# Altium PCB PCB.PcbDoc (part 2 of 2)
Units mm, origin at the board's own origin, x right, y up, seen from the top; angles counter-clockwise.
Board outline 73.15 x 70.89 mm, 4 copper layers (Top Layer, Int1 (GND), Int2 (PWR), Bottom Layer), stack 1.369 mm thick; 101 components, 61 nets, 289 pads, 185 vias.
Unrouted connection lines stored in the file: 20.
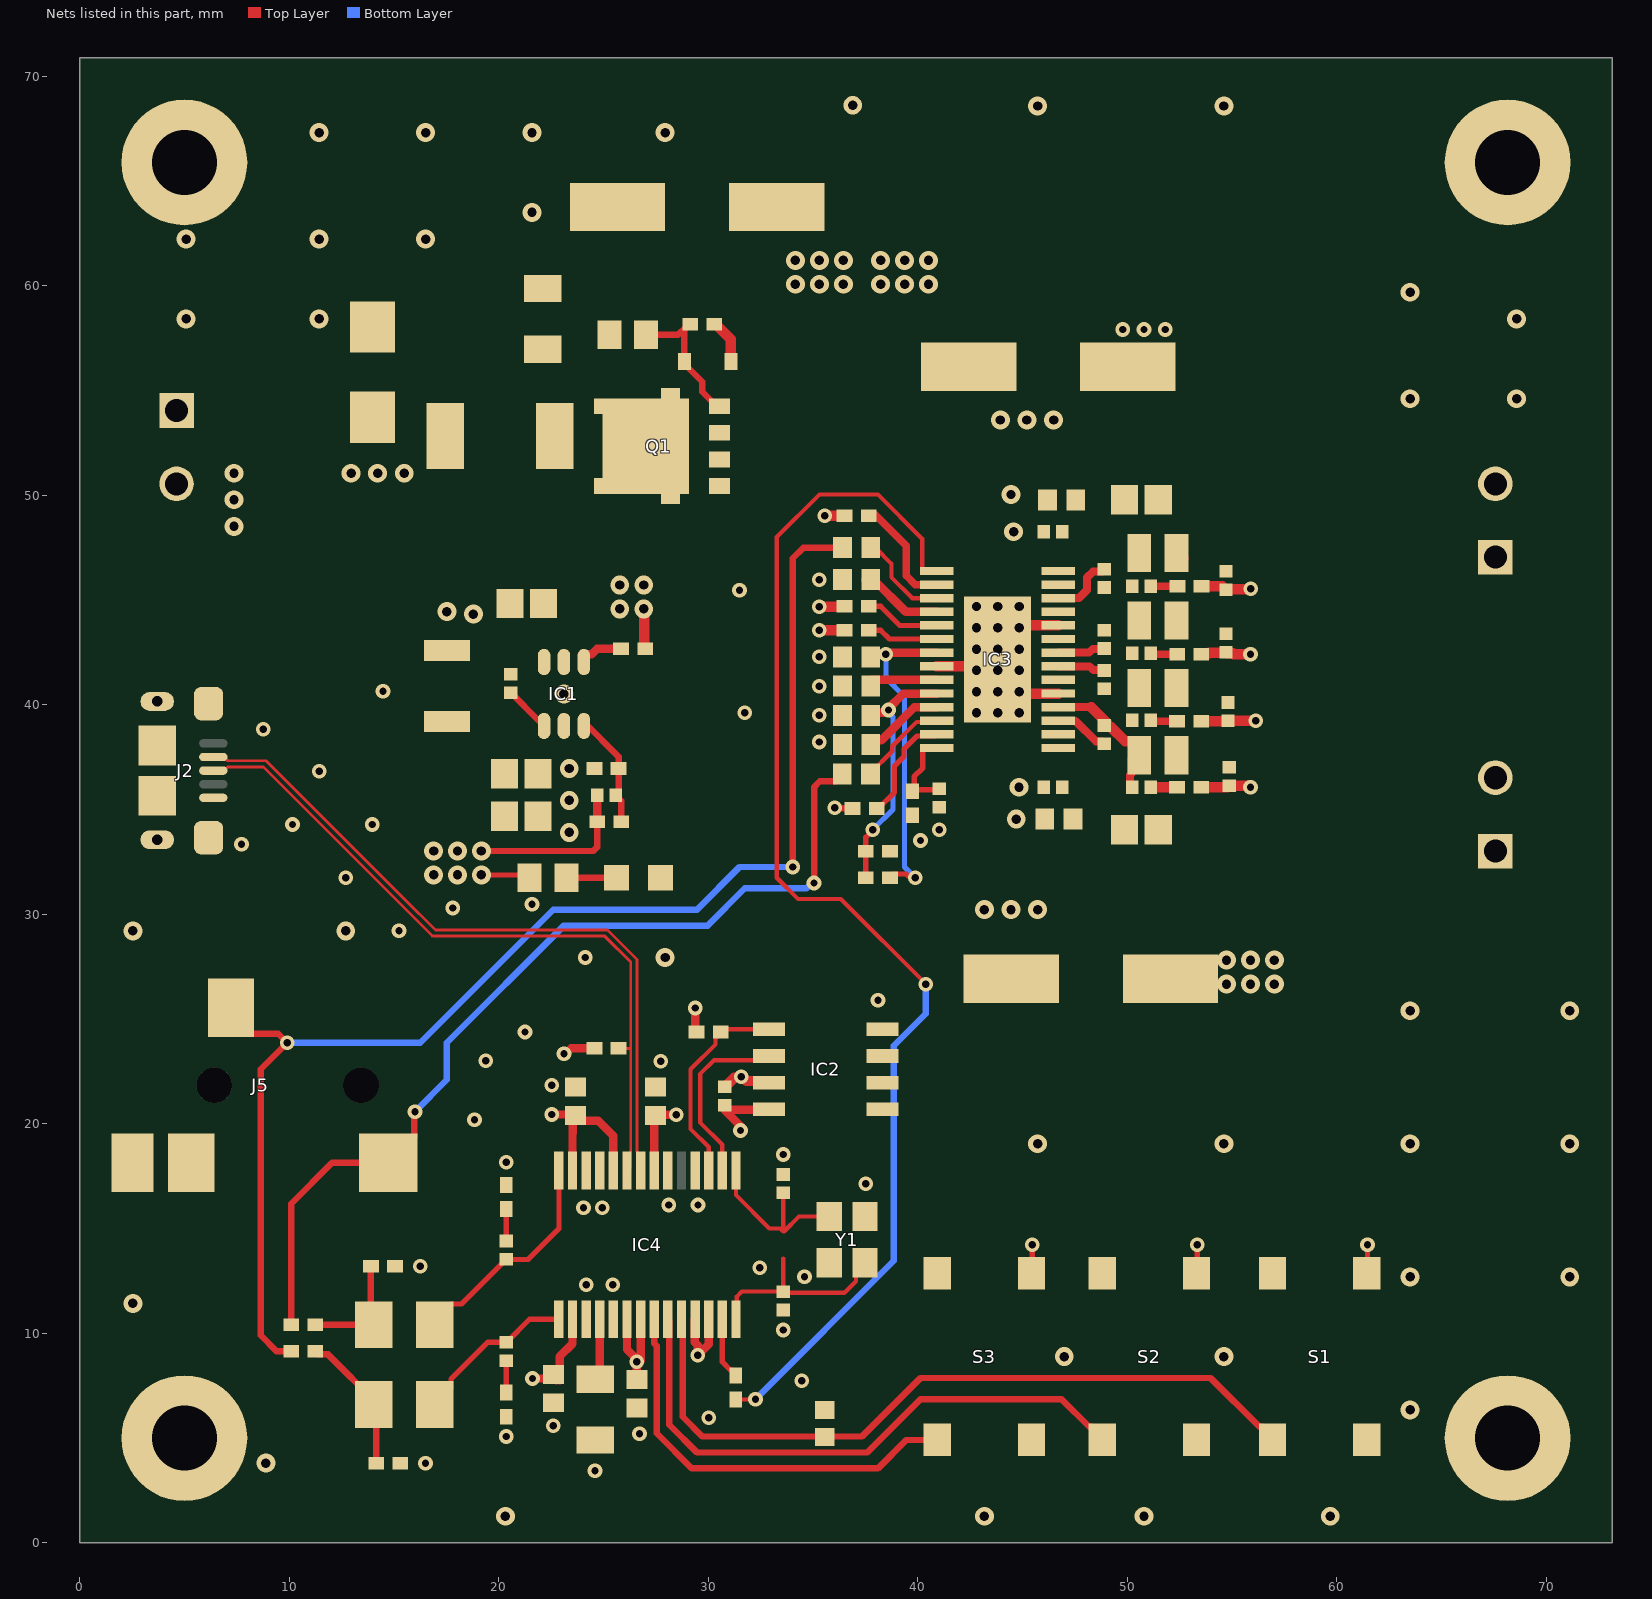
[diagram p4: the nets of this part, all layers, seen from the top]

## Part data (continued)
R4: library part RCG0402100KFKED, "RES SMD 100K OHM 1% 1/16W 0402", Device Package="0402 (1005 Metric)", Manufacturer="Vishay Dale", Operating Temperature="-55°C ~ 155°C", Power (Watts)="0.063W, 1/16W", Resistance="100 kOhms", Supplier Device Package=0402, Supplier Part Number 1=541-1751-1-ND, Temperature Coefficient=±100ppm/°C, Tolerance=±1%
R5 R7: library part SR0805JR-7W1KL, "RES 1K OHM 5% 1/4W 0805", Device Package="0805 (2012 Metric)", Manufacturer=Yageo, Operating Temperature="-55°C ~ 155°C", Power (Watts)="0.25W, 1/4W", Ratings=AEC-Q200, Supplier Device Package=0805, Supplier Part Number 1=YAG6171CT-ND, Temperature Coefficient=±100ppm/°C, Tolerance=±5%
R8: library part RMCF0603JT1M00, "RES 1M OHM 5% 1/10W 0603", Device Package="0603 (1608 Metric)", Manufacturer="Stackpole Electronics Inc", Operating Temperature="-55°C ~ 155°C", Power (Watts)="0.1W, 1/10W", Ratings=AEC-Q200, Supplier Device Package=0603, Supplier Part Number 1=RMCF0603JT1M00CT-ND, Temperature Coefficient=±200ppm/°C, Tolerance=±5%
R9 R23 R28 R29: library part JR0402X20E, "0402 20 AMP JUMPER", Device Package="0402 (1005 Metric)", Manufacturer=Ohmite, Operating Temperature="-55°C ~ 150°C", Power (Watts)="0.2W, 1/5W", Supplier Device Package=0402, Supplier Part Number 1=JR0402X20ECT-ND, Tolerance=Jumper
R11 R13 R14 R22: library part RCG0402100KFKED, "RES SMD 100K OHM 1% 1/16W 0402", Device Package="0402 (1005 Metric)", Manufacturer="Vishay Dale", Operating Temperature="-55°C ~ 155°C", Power (Watts)="0.063W, 1/16W", Supplier Device Package=0402, Supplier Part Number 1=541-1751-1-ND, Temperature Coefficient=±100ppm/°C, Tolerance=±1%
R12 R17 R20 R21: library part RMCF0402FT10R0, "RES 10 OHM 1% 1/16W 0402", Device Package="0402 (1005 Metric)", Manufacturer="Stackpole Electronics Inc", Operating Temperature="-55°C ~ 155°C", Power (Watts)="0.063W, 1/16W", Ratings=AEC-Q200, Supplier Device Package=0402, Supplier Part Number 1=RMCF0402FT10R0CT-ND, Temperature Coefficient=±100ppm/°C, Tolerance=±1%
R15: library part RMCF0402FT3K30, "RES 3.3K OHM 1% 1/16W 0402", Device Package="0402 (1005 Metric)", Manufacturer="Stackpole Electronics Inc", Operating Temperature="-55°C ~ 155°C", Power (Watts)="0.063W, 1/16W", Ratings=AEC-Q200, Supplier Device Package=0402, Supplier Part Number 1=RMCF0402FT3K30CT-ND, Temperature Coefficient=±100ppm/°C, Tolerance=±1%
R19: library part CRCW04021K50FKEDHP, "RES SMD 1.5K OHM 1% 1/5W 0402"
R24 R25: library part RK73H1ETTP1690F, "RES 169 OHM 1% 1/10W 0402", Device Package="0402 (1005 Metric)", Manufacturer="KOA Speer Electronics, Inc.", Operating Temperature="-55°C ~ 155°C", Power (Watts)="0.1W, 1/10W", Ratings=AEC-Q200, Supplier Device Package=0402, Supplier Part Number 1=2019-RK73H1ETTP1690FCT-ND, Temperature Coefficient=±100ppm/°C, Tolerance=±1%
R26 R27: library part ERJ-2RKF16R0X, "RES SMD 16 OHM 1% 1/10W 0402", Device Package="0402 (1005 Metric)", Manufacturer="Panasonic Electronic Components", Operating Temperature="-55°C ~ 155°C", Power (Watts)="0.1W, 1/10W", Ratings=AEC-Q200, Supplier Device Package=0402, Supplier Part Number 1=P16.0LCT-ND, Temperature Coefficient=±100ppm/°C, Tolerance=±1%
S1 S2 S3: "SWITCH TACTILE SPST-NO 0.05A 12V", Contact Rating @ Voltage="0.05A @ 12VDC", Manufacturer=C&K, Operating Force=160gf, Operating Temperature="-20°C ~ 60°C", Supplier Part Number 1=CKN9112CT-ND
Y1: library part ABM8G-12.000MHZ-B4Y-T, "CRYSTAL 12.0000MHZ 10PF SMD", Device Package="4-SMD, No Lead", ESR (Equivalent Series Resistance)="120 Ohms", Frequency Stability=±30ppm, Load Capacitance=10pF, Manufacturer="Abracon LLC", Operating Mode=Fundamental, Operating Temperature="-20°C ~ 70°C", Supplier Part Number 1=535-10283-1-ND

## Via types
v1: diameter 0.9, hole 0.45, Top Layer to Bottom Layer, tented both sides, 105 vias
v2: diameter 0.7, hole 0.35, Top Layer to Bottom Layer, tented both sides, 80 vias

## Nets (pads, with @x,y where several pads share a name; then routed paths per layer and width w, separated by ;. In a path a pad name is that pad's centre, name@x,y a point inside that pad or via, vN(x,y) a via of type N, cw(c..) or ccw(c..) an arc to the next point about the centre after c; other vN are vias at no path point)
+3V3: C4.2 C5.2 C6.2 C10.2 C25.2 C29.2 C36.2 C37.2 IC2.8 IC4.7 IC4.10 IC4.13 IC4.16 IC4.20 IC4.21 IC4.25 IC4.26 L1.2 R2.1 R7.2 R15.1 R19.1 S1.3 S1.4 S2.3 S2.4 S3.3 S3.4 | length 45.3
  Top Layer w0.254: v1(19.177,31.881) 21.346,31.881 R7.2@21.477,31.75 ; S3.4@45.43,12.865 45.466,12.901 v2(45.466,14.224) ; S2.4@53.304,12.865 53.34,12.901 v2(53.34,14.224) ; S1.4@61.432,12.865 61.468,12.901 v2(61.468,14.224)
  Top Layer w0.305: v1(19.177,33.024) 24.511,33.024 24.698,33.211 R2.1@24.698,34.421
  Top Layer w0.4: v2(21.613,7.848) 22.669,7.848 C36.2@22.756,7.761 ; v2(22.527,20.447) 23.63,20.447 C37.2@23.67,20.407 ; C36.2@22.908,7.761 22.908,8.89 23.524,9.506 IC4.16@23.524,10.674 ; v2(23.114,23.349) 23.195,23.349 23.449,23.603 R19.1@24.571,23.603 ; IC4.13@23.524,17.774 23.524,19.539 23.543,19.558 23.543,20.28 C37.2@23.67,20.407 ; R2.1@24.698,34.421 24.706,34.429 C4.2@24.706,35.691 ; IC4.10@25.474,17.774 25.474,19.43 24.748,20.157 23.92,20.157 C37.2@23.67,20.407 ; IC4.20@26.124,10.674 26.124,9.23 26.718,8.636 26.774,8.692 IC4.21@26.774,10.674 ; C29.2@26.592,7.793 v2(26.592,8.642) ; IC4.7@27.424,17.774 27.424,20.351 C25.2@27.48,20.407 27.511,20.437 v2(28.469,20.437) ; R15.1@29.37,24.384 29.385,24.399 v2(29.385,25.527) ; IC4.25@29.374,10.674 29.351,10.65 29.351,9.585 29.494,9.441 v2(29.494,8.949) 30.02,9.476 30.02,10.67 IC4.26@30.024,10.674 ; v2(31.544,19.685) 31.544,19.899 30.782,20.661 30.802,20.681 32.876,20.681 IC2.8@32.896,20.701
  other v1: 16.891,31.881 18.034,31.881 16.891,33.024 18.034,33.024
+15V: C2.1 C3.2 C11.1 C42.1 D1.2 FB5.2 FB10.2 IC1.5 Q1.1 Q1.2 Q1.3 R1.2 R3.2 R11.2 R13.2 R22.2 | length 7.1
  Top Layer w0.305: v2(36.04,35.08) 36.054,35.066 36.876,35.066 R22.2@36.89,35.052
  Top Layer w0.5: v1(26.924,44.577) 26.958,44.543 26.958,42.706 R1.2@26.991,42.672 ; R3.2@30.293,58.166 30.368,58.166 31.084,57.45 D1.2@31.084,56.388 ; v2(35.306,44.679) 35.319,44.691 36.496,44.691 R13.2@36.509,44.704 ; v2(35.56,49.022) R11.2@36.509,49.022
  other v1: 54.737,26.67 55.88,26.67 57.023,26.67 54.737,27.813 55.88,27.813 57.023,27.813 25.781,44.577 25.781,45.72 26.924,45.72 34.163,60.071 35.306,60.071 36.449,60.071 38.227,60.071 39.37,60.071 40.513,60.071 34.163,61.214 35.306,61.214 36.449,61.214 38.227,61.214 39.37,61.214 40.513,61.214
  other v2: 49.784,57.912 50.8,57.912 51.816,57.912
A_SCL: IC2.6 IC4.2 | length 8.7
  Top Layer w0.203: IC4.2@30.674,17.774 30.674,19.005 29.614,20.066 29.614,22.377 30.274,23.038 32.693,23.038 IC2.6@32.896,23.241
A_SDA: IC2.5 IC4.3 R15.2 | length 9.9
  Top Layer w0.203: IC4.3@30.024,17.774 30.024,18.893 29.158,19.76 29.158,22.607 30.347,23.796 30.347,24.06 30.797,24.511 IC2.5@32.896,24.511
AUD_D_N: IC4.8 J2.2 | length 34.4
  Top Layer w0.141: J2.2@6.379,37.51 6.888,37.51 7.066,37.332 8.896,37.332 15.39,30.838 15.494,30.734 16.979,29.249 25.189,29.249 26.596,27.842 26.596,23.622 26.596,18.686 26.62,18.662 26.62,17.928 IC4.8@26.774,17.774
AUD_D_P: IC4.9 J2.3 R19.2 | length 34.5
  Top Layer w0.141: J2.3@6.379,36.86 6.888,36.86 7.066,37.038 8.775,37.038 16.771,29.042 16.857,28.956 25.067,28.956 26.303,27.721 26.303,23.622 ; R19.2@25.721,23.603 26.284,23.603 26.303,23.622 ; IC4.9@26.124,17.774 26.279,17.928 26.279,18.662 26.303,18.686 26.303,23.622
AUDIO_INL: C32.1 J5.2 R29.1 | length 45
  Top Layer w0.305: R29.1@10.093,10.414 10.093,16.189 12.048,18.144 J5.2@14.726,18.144 15.974,19.392 15.974,20.546 v2(16.002,20.574) ; v2(35.052,31.496) 35.052,36.068 35.33,36.346 36.099,36.346 36.397,36.644 C32.1@36.397,36.694
  Bottom Layer w0.305: v2(16.002,20.574) 17.526,22.098 17.526,23.876 23.114,29.464 29.972,29.464 31.75,31.242 34.691,31.242 34.945,31.496 v2(35.052,31.496)
AUDIO_INR: C14.1 J5.3 R28.1 | length 64.7
  Top Layer w0.305: J5.3@7.226,25.544 7.226,25.244 8.174,24.296 9.486,24.296 v2(9.906,23.876) 8.636,22.606 8.636,9.906 9.398,9.144 R28.1@10.093,9.144 ; v2(34.036,32.258) 34.036,46.99 34.544,47.498 C14.1@36.409,47.498
  Bottom Layer w0.305: v2(9.906,23.876) 16.256,23.876 22.606,30.226 29.464,30.226 31.496,32.258 v2(34.036,32.258)
AVCC_MP: C19.2 IC3.7 R16.1 | length 15.9
  Top Layer w0.254: R16.1@38.675,31.75 38.848,31.923 39.451,31.923 39.539,31.835 39.793,31.835 v2(39.878,31.75)
  Top Layer w0.406: C19.2@37.759,42.291 37.957,42.489 38.028,42.418 v2(38.481,42.418) 38.552,42.489 IC3.7@40.915,42.489
  Bottom Layer w0.254: v2(38.481,42.418) 38.481,41.275 39.37,40.386 39.37,32.258 v2(39.878,31.75)
EN_AMP: IC3.1 R9.1 | length 60.5
  Top Layer w0.203: R9.1@31.328,6.83 R9.1@31.316,6.842 32.242,6.842 v2(32.258,6.858) ; v2(40.386,26.67) 36.322,30.734 34.29,30.734 33.274,31.75 33.274,48.006 35.306,50.038 38.1,50.038 40.217,47.921 40.217,46.487 40.315,46.389 IC3.1@40.915,46.389
  Bottom Layer w0.305: v2(32.258,6.858) 38.862,13.462 38.862,23.725 40.386,25.249 v2(40.386,26.67)
GAIN0: IC3.5 R13.1 | length 3.6
  Top Layer w0.254: R13.1@37.659,44.704 38.227,44.704 39.142,43.789 IC3.5@40.915,43.789
GAIN1: IC3.6 R14.1 | length 3.4
  Top Layer w0.254: R14.1@37.659,43.561 38.227,43.561 38.649,43.139 IC3.6@40.915,43.139
GND: C2.2 C3.1 C5.1 C6.1 C7.1 C8.2 C9.2 C10.1 C11.2 C12.1 C13.1 C16.1 C18.1 C19.1 C22.1 C23.2 C25.1 C27.1 C28.1 C29.1 C30.1 C31.1 C35.1 C36.1 C37.1 C38.1 C40.1 C41.1 C42.2 D2.1 D3.2 H1.1 H2.1 H3.1 H4.1 IC1.2 IC2.1 IC2.2 IC2.3 IC2.4 IC2.7 IC3.8 IC3.19 IC3.24 IC3.EPAD IC4.4 IC4.6 IC4.11 IC4.12 IC4.17 IC4.19 J1.1 J2.5 J2.S J5.1 J5.4 R4.2 R5.1 R12.2 R14.2 R17.2 R18.2 R20.1 R21.2 R23.1 R24.1 R25.1 R26.1 R27.1 Y1.2 Y1.4 | length 18.9
  Top Layer w0.5: C10.1@30.782,21.776 30.802,21.776 v2@31.233,22.206 ; v2(31.579,22.244) 31.633,22.244 31.831,22.046 32.821,22.046 IC2.7@32.896,21.971 ; v2(35.306,43.561) R14.2@36.509,43.561 ; IC3.8@40.915,41.839 42.611,41.839 v1(42.805,41.645) ; v1(44.837,40.629) 44.927,40.539 IC3.19@46.715,40.539 ; v1(44.837,43.677) 44.949,43.789 IC3.24@46.715,43.789 ; R21.2@53.525,36.068 54.776,36.068 54.844,36.136 C35.1@54.864,36.136 55.758,36.136 55.826,36.068 v2(55.88,36.068) ; R20.1@53.525,39.21 53.535,39.221 54.797,39.221 C27.1@54.807,39.231 54.812,39.236 56.125,39.236 v2(56.13,39.24) ; R17.2@53.534,42.418 53.584,42.468 53.905,42.468 53.922,42.484 C22.1@54.681,42.484 ; R12.2@53.545,45.654 54.538,45.654 54.692,45.5 C18.1@54.712,45.5 54.729,45.517 55.882,45.517 v2(55.899,45.534) ; C22.1@54.712,42.514 54.762,42.464 55.028,42.464 55.074,42.418 v2(55.88,42.418)
  other v1: 20.32,1.27 43.18,1.27 50.8,1.27 59.69,1.27 8.89,3.81 63.5,6.35 46.99,8.89 54.61,8.89 2.54,11.43 63.5,12.7 71.12,12.7 45.72,19.05 54.61,19.05 63.5,19.05 71.12,19.05 63.5,25.4 71.12,25.4 27.94,27.94 2.54,29.21 12.7,29.21 43.18,30.226 44.45,30.226 45.72,30.226 23.368,33.913 44.704,34.544 23.368,35.437 44.831,36.068 23.368,36.961 42.805,39.613 43.821,39.613 44.837,39.613 23.114,40.517 42.805,40.629 43.821,40.629 43.821,41.645 44.837,41.645 42.805,42.661 43.821,42.661 44.837,42.661 42.805,43.677 43.821,43.677 18.796,44.327 17.526,44.45 42.805,44.693 43.821,44.693 44.837,44.693 44.577,48.26 44.45,50.038 43.942,53.594 45.212,53.594 46.482,53.594 63.5,54.61 68.58,54.61 5.08,58.42 11.43,58.42 68.58,58.42 63.5,59.69 5.08,62.23 11.43,62.23 16.51,62.23 21.59,63.5 11.43,67.31 16.51,67.31 21.59,67.31 27.94,67.31 45.72,68.58 54.61,68.58 36.901,68.618
  other v2: 24.597,3.448 16.51,3.81 20.368,5.08 26.718,5.207 22.602,5.587 30.02,5.969 34.465,7.747 33.576,10.16 24.178,12.319 25.448,12.319 34.592,12.7 32.459,13.132 16.256,13.208 24.051,16.002 24.94,16.002 28.115,16.129 29.512,16.129 37.513,17.145 20.368,18.161 33.576,18.542 18.844,20.193 22.527,21.844 27.734,22.987 19.383,23.02 21.257,24.384 38.1,25.908 24.13,27.94 15.24,29.21 17.81,30.303 21.59,30.48 12.7,31.75 7.726,33.345 40.132,33.528 41.021,34.036 10.16,34.29 13.97,34.29 11.43,36.83 35.306,38.227 8.759,38.831 35.306,39.497 31.75,39.624 14.478,40.64 35.306,40.894 35.306,42.291 31.496,45.466 35.306,45.974
LOUTN: C27.2 FB8.2 J4.2
LOUTP: C35.2 FB9.2 J4.1
NetC1_1: C1.1 IC1.1 | length 2.1
  Top Layer w0.305: C1.1@20.574,40.585 21.913,39.246 IC1.1@22.164,39.246
NetC1_2: C1.2 IC1.6 L1.1
NetC4_1: C4.1 IC1.3 R2.2 R4.1 | length 5.7
  Top Layer w0.305: IC1.3@24.064,39.246 24.064,39.186 25.721,37.529 R4.1@25.721,36.961 25.721,35.826 C4.1@25.586,35.691 25.848,35.429 R2.2@25.848,34.421
NetC7_2: C7.2 F1.2 Q1.5 Q1.6 Q1.7 Q1.8 Q1.9
NetC8_1: C8.1 IC4.1 R8.1 Y1.1 | length 8.5
  Top Layer w0.203: IC4.1@31.324,17.774 31.324,16.603 32.916,15.012 33.439,15.012 33.576,14.874 ; C8.1@33.576,16.705 33.576,14.874 ; Y1.1@35.774,15.578 34.33,15.578 33.626,14.874 33.576,14.874
NetC9_1: C9.1 IC4.28 R8.2 Y1.3 | length 9.8
  Top Layer w0.203: IC4.28@31.324,10.674 31.366,10.716 31.366,11.76 31.603,11.997 C9.1@33.576,11.997 ; 33.576,13.574 C9.1@33.576,11.997 ; Y1.3@37.474,13.378 37.052,12.955 37.052,12.492 36.497,11.938 33.635,11.938 C9.1@33.576,11.997
NetC12_2: C12.2 C13.2 FB5.1 IC3.27 IC3.28
NetC14_2: C14.2 IC3.3 | length 4.5
  Top Layer w0.203: C14.2@37.759,47.498 37.979,47.498 38.748,46.729 38.748,46.084 39.743,45.089 IC3.3@40.915,45.089
NetC15_1: C15.1 IC3.26 | length 3.1
  Top Layer w0.381: IC3.26@46.715,45.089 46.724,45.099 47.703,45.099 48.078,45.473 48.078,46.075 48.372,46.368 48.784,46.368 C15.1@48.894,46.478
NetC15_2: C15.2 C17.1 FB6.1 IC3.25
NetC16_2: C16.2 IC3.4 | length 4.1
  Top Layer w0.406: C16.2@37.496,45.974 C16.2@37.759,45.974 37.893,45.974 39.428,44.439 IC3.4@40.915,44.439
NetC17_2: C17.2 R12.1 | length 1.3
  Top Layer w0.356: C17.2@51.124,45.654 R12.1@52.395,45.654
NetC20_1: C20.1 IC3.22 | length 2.3
  Top Layer w0.381: IC3.22@46.715,42.489 48.179,42.489 48.362,42.672 48.878,42.672 C20.1@48.895,42.689
NetC20_2: C20.2 C21.1 FB7.1 IC3.23
NetC21_2: C21.2 R17.1 | length 1.3
  Top Layer w0.356: C21.2@51.113,42.418 R17.1@52.384,42.418
NetC23_1: C23.1 IC3.9 | length 3.1
  Top Layer w0.406: C23.1@37.747,41.029 C23.1@37.755,41.021 ; C23.1@37.793,41.189 39.075,41.189 IC3.9@40.915,41.189
NetC24_1: C24.1 IC3.21 | length 2.3
  Top Layer w0.381: IC3.21@46.715,41.839 48.204,41.839 48.387,41.656 48.878,41.656 C24.1@48.895,41.639
NetC24_2: C24.2 C26.1 FB8.1 IC3.20
NetC26_2: C26.2 R20.2 | length 1.3
  Top Layer w0.356: C26.2@51.124,39.263 51.177,39.21 R20.2@52.375,39.21
NetC28_2: C28.2 IC4.18 | length 3.5
  Top Layer w0.4: C28.2@24.661,7.455 24.661,7.753 C28.2@24.661,8.052 ; C28.2@24.763,7.8 24.824,7.862 IC4.18@24.824,10.674
NetC30_2: C30.2 IC3.10 R16.2 R18.1 | length 12
  Top Layer w0.254: R16.2@37.525,31.75 37.525,33.681 37.846,34.002 v2(37.846,34.036)
  Top Layer w0.406: C30.2@37.714,39.624 v2@38.405,39.624 ; v2@38.57,39.789 39.32,40.539 IC3.10@40.915,40.539
  Bottom Layer w0.254: v2(37.846,34.036) 38.817,35.007 38.817,39.421 38.608,39.63 v2(38.608,39.751)
NetC31_2: C31.2 IC3.11 | length 3.8
  Top Layer w0.406: C31.2@37.747,38.308 38.265,38.308 39.845,39.889 IC3.11@40.915,39.889
NetC32_2: C32.2 IC3.12 | length 4.4
  Top Layer w0.203: C32.2@37.747,36.694 37.747,36.744 38.786,37.783 38.786,38.021 39.947,39.182 40.858,39.182 IC3.12@40.915,39.239
NetC33_1: C33.1 IC3.17 | length 2.6
  Top Layer w0.381: IC3.17@46.715,39.239 46.724,39.229 47.532,39.229 48.518,38.244 48.786,38.244 C33.1@48.895,38.134
NetC33_2: C33.2 C34.1 FB9.1 IC3.18 | length 6.5
  Top Layer w0.381: IC3.18@46.715,39.889 48.273,39.889 ; C34.1@50.13,36.254 50.13,36.649 50.191,36.711 50.191,37.442 FB9.1@50.341,37.592
  Top Layer w0.5: 48.273,39.889 C33.2@49.021,39.142 ; C33.2@48.964,39.064 48.964,38.964 49.198,38.964 49.91,38.252 50.25,38.252 50.57,37.932 FB9.1@50.57,37.592
NetC34_2: C34.2 R21.1 | length 1.1
  Top Layer w0.5: C34.2@51.124,36.068 R21.1@52.257,36.068
NetC38_2: C38.2 IC3.14 R23.2 | length 4.1
  Top Layer w0.254: R23.2@39.751,35.881 R23.2@39.811,35.941 ; IC3.14@40.915,37.939 40.315,37.939 40.242,37.866 40.242,36.991 39.827,36.576 39.827,35.957 R23.2@39.811,35.941 ; C38.2@41.021,36 40.962,35.941 R23.2@39.811,35.941
NetC39_2: C39.2 R24.2 R28.2 | length 6.8
  Top Layer w0.305: R28.2@11.243,9.144 11.391,8.996 11.857,8.996 14.157,6.696 R24.2@14.157,3.81
NetC40_2: C40.2 C41.2 FB10.1 IC3.15 IC3.16
NetC43_2: C43.2 R25.2 R29.2 | length 5.6
  Top Layer w0.305: R29.2@11.243,10.414 C43.2@14.034,10.414 13.903,10.545 R25.2@13.903,13.208
NetC44_1: C44.1 R26.2 | length 1.5
  Top Layer w0.254: C44.1@20.368,14.41 R26.2@20.368,15.935
NetC45_1: C45.1 R27.2 | length 1.5
  Top Layer w0.254: R27.2@20.368,7.179 C45.1@20.368,8.704
NetD1_1: D1.1 Q1.4 R3.1 R5.2 | length 6.9
  Top Layer w0.305: R5.2@27.037,57.658 28.56,57.658 R3.1@28.92,58.018 ; R3.1@29.143,58.166 29.068,58.166 R3.1@28.92,58.018 ; Q1.4@30.537,54.249 30.412,54.249 29.718,54.943 29.718,55.427 28.86,56.286 D1.1@28.86,56.388 28.86,57.883 28.92,57.943 R3.1@28.92,58.018
NetD2_2: D2.2 F1.1 J1.2
  other v1: 7.366,48.514 7.366,49.784 7.366,51.054 12.954,51.054 14.224,51.054 15.494,51.054
NetD3_1: D3.1 R7.1 | length 2.4
  Top Layer w0.305: R7.1@23.227,31.75 D3.1@25.62,31.75
NetIC1_4: IC1.4 R1.1 | length 2.2
  Top Layer w0.4: IC1.4@24.064,42.042 24.064,42.313 24.156,42.405 24.427,42.405 24.694,42.672 R1.1@25.841,42.672
NetIC3_2: IC3.2 R11.1 | length 5.2
  Top Layer w0.356: R11.1@37.965,49.062 39.442,47.585 39.442,46.17 39.874,45.739 IC3.2@40.915,45.739
NetIC3_13: IC3.13 R22.1 | length 5.3
  Top Layer w0.254: R22.1@38.04,35.052 38.115,35.052 38.887,35.824 38.887,37.084 39.345,37.541 39.345,37.897 39.964,38.516 40.842,38.516 IC3.13@40.915,38.589
ROUTN: C22.2 FB7.2 J3.1
ROUTP: C18.2 FB6.2 J3.2 | length 0.3
  Top Layer w1: FB6.2@52.35,47.244 52.35,47.06 FB6.2@52.42,46.99
SSPND: IC4.27 R9.2 | length 3
  Top Layer w0.254: IC4.27@30.674,10.674 30.674,8.633 31.068,8.24 31.143,8.24 31.316,8.067 R9.2@31.316,7.992
VOL_DOWN: IC4.24 S1.1 S1.2 | length 35.7
  Top Layer w0.305: IC4.24@28.724,10.674 28.777,10.621 28.777,6.021 29.718,5.08 37.338,5.08 40.132,7.874 53.973,7.874 56.309,5.538 56.434,5.538 56.932,5.04 S1.1@56.932,4.915
VOL_MUTE: IC4.22 S3.1 S3.2 | length 20.1
  Top Layer w0.305: IC4.22@27.424,10.674 27.431,10.667 27.431,9.519 27.539,9.41 27.539,5.227 29.21,3.556 38.1,3.556 39.459,4.915 S3.1@40.93,4.915
VOL_UP: IC4.23 S2.1 S2.2 | length 28.2
  Top Layer w0.305: IC4.23@28.074,10.674 28.147,10.601 28.147,9.749 28.148,9.748 28.148,5.634 29.464,4.318 37.592,4.318 40.132,6.858 46.861,6.858 48.181,5.538 48.306,5.538 48.804,5.04 S2.1@48.804,4.915
VOUTL: C43.1 C44.2 IC4.14 | length 10.7
  Top Layer w0.254: C43.1@16.954,10.414 16.954,10.629 17.727,11.402 18.221,11.402 20.348,13.53 C44.2@20.368,13.53 21.404,13.53 22.874,15 IC4.14@22.874,17.774
VOUTR: C39.1 C45.2 IC4.15 | length 7.9
  Top Layer w0.254: C39.1@16.954,6.604 17.727,7.377 17.727,7.821 19.49,9.584 C45.2@20.368,9.584 20.388,9.584 21.478,10.674 IC4.15@22.874,10.674
pads on no net: IC4.5 J2.1 J2.4 J5.M
copper on no net:
  other v2: 19.05,27.94

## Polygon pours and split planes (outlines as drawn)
+15V on Top Layer "Top Layer-+15V" (solid, pour order 1): 35.052,52.07 39.116,52.07 39.116,58.42 47.752,58.42 47.752,51.955 50.939,48.768 59.436,48.768 59.436,66.802 30.48,66.802 30.48,56.896 29.718,56.896 29.718,49.784 32.766,49.784
+3V3 on Top Layer "+3V3_L01_P078" (solid, pour order 78): 19.558,39.878 20.828,38.608 20.828,30.988 16.256,30.988 15.494,31.75 15.494,39.624 15.748,39.878
NetC1_2 on Top Layer "NETC1_2_L01_P077" (solid, pour order 77): 22.352,41.402 16.256,41.402 16.256,43.18 21.59,43.18 22.352,42.418
+15V on Top Layer "Top Layer-+15V 1" (solid, pour order 76): 22.606,42.164 23.622,42.164 23.622,43.18 24.384,43.942 27.686,43.942 27.686,46.736 21.59,46.736 21.59,44.196 21.463,44.069 22.606,42.926
LOUTP on Top Layer "LOUTP_L01_P073" (solid, pour order 73): 52.07,36.83 57.912,36.83 62.992,31.75 68.834,31.75 68.834,34.29 65.278,34.29 60.96,38.608 52.07,38.608
LOUTN on Top Layer "LOUTN_L01_P072" (solid, pour order 72): 51.816,41.971 65.471,41.971 68.834,38.608 68.834,35.56 65.786,35.56 61.622,39.724 51.816,39.724
ROUTN on Top Layer "ROUTN_L01_P071" (solid, pour order 71): 52.07,44.958 62.992,44.958 66.294,48.26 69.088,48.26 69.088,46.482 65.431,42.825 52.07,42.825
ROUTP on Top Layer "ROUTP_L01_P070" (solid, pour order 70): 55.626,46.228 62.484,46.228 65.786,49.53 69.088,49.53 69.088,52.324 65.024,52.324 60.96,48.26 51.816,48.26 51.816,46.228 51.816,48.26 51.816,46.228
NetC7_2 on Top Layer "NETC7_2_L01_P062" (solid, pour order 62): 20.828,55.626 20.574,55.626 20.574,58.674 26.416,58.674 28.956,56.134 28.956,47.498 20.828,47.498
NetD2_2 on Top Layer "NETD2_2_L01_P061" (solid, pour order 61): 3.302,52.07 7.366,52.07 9.652,54.356 19.304,54.356 19.304,46.228 3.302,46.228
NetC40_2 on Top Layer "NETC40_2_L01_P039" (solid, pour order 39): 45.844,38.854 45.844,37.757 46.606,36.995 46.606,35.471 46.987,35.09 46.987,32.931 50.543,32.931 50.543,35.09 50.162,35.09 47.622,37.63 47.622,38.854
NetC12_2 on Top Layer "NETC12_2_L01_P036" (solid, pour order 36): 50.543,50.838 46.987,50.838 46.987,49.06 46.606,48.679 46.606,47.409 45.717,46.52 45.717,45.546 47.486,45.546 47.647,45.707 47.647,46.418 48.384,47.155 50.035,48.806 50.543,48.806
NetC15_2 on Top Layer "Top Layer-NetC67_2" (solid, pour order 43): 48.943,45.758 47.85,44.666 47.063,44.666 47.063,44.285 48.155,44.285 48.536,44.666 49.425,44.666 50.594,45.834 50.594,46.291 51.051,46.291 51.051,47.79 50.035,47.79 49.343,47.098 49.343,45.758
NetC20_2 on Top Layer "NETC20_2_L01_P059" (solid, pour order 59): 46.428,43.37 46.428,42.989 48.003,42.989 48.333,43.32 49.908,43.32 49.908,42.126 50.543,42.126 50.543,43.142 50.644,43.243 51.051,43.243 51.051,44.209 48.562,44.209 47.723,43.37 47.342,43.37
NetC24_2 on Top Layer "NETC24_2_L01_P035" (solid, pour order 35): 46.911,41.44 46.911,41.008 47.901,41.008 48.612,40.297 49.679,40.297 49.933,40.043 49.933,39.408 50.543,39.408 50.543,39.992 50.848,40.297 51.051,40.297 51.051,41.313 49.933,41.313 49.705,41.084 48.409,41.084 48.054,41.44
GND on Top Layer "GND_L01_P080" (solid, remove dead copper, pour order 80): 0,-1.524 0,71.628 75.946,71.628 75.946,-1.524
+15V on Top Layer "+15V_L01_P003" (solid, pour order 3): 58.382,34.836 50.797,34.836 50.797,25.654 59.182,25.654 59.182,34.036
GND on Bottom Layer "GND_L04_P058" (solid, remove dead copper, pour order 58): 0,-7.112 0,72.644 76.962,72.644 76.962,-7.112
+3V3 on Int2 (PWR) "Int2 (PWR)-+3V3" (solid, pour order 68): 0,-0.508 73.66,-0.508 73.914,-0.762 73.914,24.13 41.656,24.13 29.21,36.576 20.32,36.576 19.812,37.084 19.812,44.45 0,44.45
NetD2_2 on Int2 (PWR) "NETD2_2_L03_P066" (solid, pour order 66): 0,57.15 17.272,57.15 17.272,46.482 0,46.482
+15V on Int2 (PWR) "+15V_L03_P063" (solid, pour order 63): 28.194,71.628 28.194,56.134 21.336,49.276 21.336,38.1 30.226,38.1 42.926,25.4 74.168,25.4 74.168,26.924 74.168,71.628
GND on Int1 (GND) "GND_L02_P081" (solid, pour order 81): 0,-0.508 73.66,-0.508 73.152,0 73.152,70.866 0.254,70.866 0,70.612

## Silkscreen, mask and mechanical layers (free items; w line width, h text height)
Top Overlay:
  drawing of 26 lines, arcs and shapes, not listed
  text "POWER" at 1.27,58.674 h1.2
  text "-" at 4.064,56.658 h2
  text "15 + 15  / WATTS" at 58.523,56.425 h1.3
  text "RP" at 60.808,49.784 h1.2
  text "MAX 18VDC" at 11.176,47.734 h1.2 r90
  text "RN" at 60.808,46.482 h1.2
  text "+" at 4.064,46.149 h2
  text "RIGHT" at 64.262,42.672 h1.3
  text "USB" at 1.27,41.91 h1.2
  text "LN" at 60.808,35.946 h1.2
  text "LP" at 60.808,32.39 h1.2
  text "SPEAKER OUTPUT" at 59.436,32.004 h1.2 r90
  text "PWR" at 25.59,29.4 h0.9
  text "LEFT" at 64.516,28.702 h1.3
  text "AUDIO IN/OUT" at 1.016,26.924 h1.2
  text "USB AUIDO / AMPLIFIER" at 59.33,21.376 h1.3
  text "V1.1" at 63.442,19.017 h1.1
  text "VOLUME" at 48.206,17.726 h1.1
  text "MUTE" at 41.348,14.932 h1.1
  text "UP" at 50.492,14.932 h1.1
  text "DOWN" at 57.096,14.932 h1.1
Bottom Overlay:
  drawing of 16 lines, arcs and shapes, not listed
  text "2 x 15W" at 43.184,55.923 h4
  text "USB AUDIO AMPLIFIER" at 55.88,50.843 h4
  text "V1.1" at 38.098,46.99 h2
  text "Designed By: Nikhil Kakade" at 64.77,1.552 h1.5
Mechanical 1:
  the board outline again, w0.1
